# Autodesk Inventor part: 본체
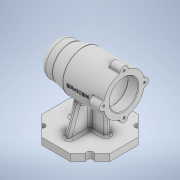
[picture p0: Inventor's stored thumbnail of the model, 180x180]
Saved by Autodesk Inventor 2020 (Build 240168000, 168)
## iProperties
Created: 2021-01
Part Number: 본체
Material: 일반
Document SubType Name: Modeling
Designer: PC2-15
Density: 1 g/cm^3
Appearance: 기본값
Author: PC2-15
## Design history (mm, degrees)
sketch "스케치1"
  geometry: L1 (-50, -20.711)-(-50, 20.711); L2 (-50, 20.711)-(-20.711, 50); L3 (-20.711, 50)-(20.711, 50); L4 (20.711, 50)-(50, 20.711); L5 (50, 20.711)-(50, -20.711); L6 (50, -20.711)-(20.711, -50); L7 (20.711, -50)-(-20.711, -50); L8 (-20.711, -50)-(-50, -20.711); 3 further points
  constraints: 16 end point, 1 coincident, 1 midpoint, 1 vertical alignment, 17 other
  dimensions: "d0" = 50 horizontal distance of L1.start point (0, -50)
extrude "돌출1" new body sketch "스케치1" distance "d1" = 10; taper "d2" = 0 deg
sketch "스케치2"
  geometry: L1 (50, 20.711)-(20.711, 50) reference; L2 (0, 0)-(35.355, 35.355); C1 r 4.5 at (35.355, 35.355); 1 further point
  constraints: 2 coincident, 2 end point, 1 centre point, 1 midpoint, 4 other
  dimensions: "d3" = 9 diameter of C1
extrude "돌출2" cut sketch "스케치2" distance "d4" = 10; taper "d5" = 0 deg
node "작업 평면1"
sketch "스케치3"
  geometry: C1 r 30 at (75, 0); 1 further point
  constraints: 1 centre point, 1 horizontal alignment
  dimensions: "d10" = 60 diameter of C1; "d11" = 75 distance of point (0, 0) C1.centre
extrude "돌출3" join sketch "스케치3" distance "d12" = 60; taper "d13" = 0 deg
sketch "스케치4"
  geometry: L1 (-10, 45)-(-10, 105) reference; L2 (-10, 105)-(-30, 100); L3 (-30, 100)-(-50, 100); L4 (-50, 100)-(-50, 75); L5 (-10, 75)-(-50, 75); 1 further point
  constraints: 8 end point, 2 horizontal, 1 midpoint, 1 perpendicular
  dimensions: "d14" = 40 distance from line of L1.end L4; "d15" = 20 distance from line of L2.end L4; "d16" = 50 diameter of L3 L5
revolve "회전1" sketch "스케치4" stored, may be unused: angle "d17" = 90 deg
sketch "스케치5"
  geometry: C1 r 6 at (30, 0); A1 r 6 centre (0, 30) between (5.97, 29.4) and (-5.97, 29.4); A2 r 6 centre (0, -30) between (-5.97, -29.4) and (5.97, -29.4); A3 r 6 centre (-30, 0) between (-29.4, 5.97) and (-29.4, -5.97); 4 further points
  constraints: 6 point on circle, 4 centre point, 2 horizontal alignment, 2 vertical alignment, 11 other
  dimensions: "d18" = 12 diameter of A1; "d19" = 12 diameter of C1; "d20" = 12 diameter of A2; "d22" = 12 diameter of A3
extrude "돌출4" join sketch "스케치5" distance "d23" = 16; taper "d24" = 0 deg
sketch "스케치6"
  geometry: L1 (-10, 45)-(-10, 105) reference; L2 (50, 69.03)-(34, 69.03) reference; L3 (34, 69.03)-(34, 80.97) reference; L4 (34, 80.97)-(50, 80.97) reference; L5 (50, 104.4)-(50, 80.97) reference; L6 (50, 104.4)-(34, 104.4) reference; L7 (34, 104.4)-(34, 104.4) reference; L8 (34, 104.4)-(50, 104.4) reference; L9 (50, 80.97)-(50, 104.4) reference; L10 (50, 80.97)-(34, 80.97) reference; L11 (34, 80.97)-(34, 69.03) reference; L12 (34, 69.03)-(50, 69.03) reference; L13 (50, 45.6)-(50, 69.03) reference; L14 (50, 45.6)-(34, 45.6) reference; L15 (34, 45.6)-(34, 45.6) reference; L16 (34, 45.6)-(50, 45.6) reference; L17 (50, 69.03)-(50, 45.6) reference; L18 (50, 69)-(50, 81) reference; L19 (50, 75)-(-36.955, 75); L20 (50, 80.97)-(50, 104.4) reference; L21 (50, 96)-(35, 96); L22 (35, 96)-(35, 99); L23 (35, 99)-(-7, 99); L24 (-7, 99)-(-7, 96); L25 (-7, 96)-(-19, 96); L26 (-19, 96)-(-19, 75); 2 further points
  constraints: 14 end point, 6 perpendicular, 2 point on line, 1 midpoint, 1 vertical
  dimensions: "d25" = 42 diameter of L21 L19; "d26" = 15 distance of L21.start L21.end; "d27" = 48 diameter of L23 L19; "d28" = 42 distance of L22.end L23.end; "d29" = 12 distance of L24.end L25.end; "d30" = 42 diameter of L25 L19
revolve "회전2" sketch "스케치6" stored, may be unused: angle "d31" = 90 deg
sketch "스케치7"
  geometry: L1 (-19, 54)-(-19, 96) reference; L2 (-19, 75)-(-50, 75); L3 (-50, 50)-(-50, 100) reference; L4 (-19, 92.5)-(-37, 92.5); L5 (-37, 92.5)-(-37, 91); L6 (-37, 91)-(-41, 91); L7 (-41, 91)-(-41, 85.5); L8 (-41, 85.5)-(-44, 85.5); L9 (-44, 85.5)-(-44, 75); 1 further point
  constraints: 14 end point, 4 perpendicular, 2 midpoint, 2 point on line, 1 horizontal, 1 vertical
  dimensions: "d32" = 18 distance of L4.start L4.end; "d33" = 35 diameter of L4 L2; "d34" = 4 distance of L5.end L6.end; "d35" = 32 diameter of L6 L2; "d36" = 3 distance of L7.end L8.end; "d37" = 21 diameter of L8 L2
revolve "회전3" sketch "스케치7" stored, may be unused: angle "d38" = 90 deg
sketch "스케치10"
  geometry: L1 (10, -20.711)-(10, 20.711) reference; L2 (10, 38.537)-(10, 30.855) reference; L3 (10, 20.711)-(10, 32.173) reference; L4 (10, -32.173)-(10, -20.711) reference; L5 (10, -30.855)-(10, -38.537) reference; L6 (52.293, 19.606)-(10, 35); L7 (52.293, -19.606)-(10, -35); L8 (0, 50)-(10, 50) reference; L9 (0, -50)-(10, -50) reference; L10 (10, 38.537)-(10, 50) reference; A1 r 30 centre (75, 0) between (52.293, 19.606) and (52.293, -19.606) reference; 1 further point
  constraints: 4 end point, 2 point on circle, 2 point on line
  dimensions: "d45" = 15 distance from line of L6.end L8; "d46" = 15 distance from line of L9 L7.end; "d47" = 110 deg angle of L6 L10; "d48" = 110 deg angle of L5 L7
extrude "돌출6" join sketch "스케치10" stored distance "d49" = 8; taper "d50" = 0 deg
fillet "모깎기11" dims "d104" = 3
sketch "스케치12"
  geometry: L1 (-30, 50)-(-10, 45) reference; L2 (-10, 45)-(34, 45) reference; L3 (-38.537, 10)-(-30.855, 10) reference; L4 (-20.711, 10)-(-32.173, 10) reference; L5 (20.711, 10)-(-20.711, 10) reference; L6 (-19.724, 47.431)-(-27, 10); L7 (-50, 0)-(-50, 10) reference; L8 (-38.537, 10)-(-50, 10) reference; L9 (-19.724, 47.431)-(-10, 45); L10 (-4, 52.293)-(-4, 10) reference; L11 (-4, 45)-(-4, 10); L12 (-4, 10)-(-27, 10); L13 (-10, 45)-(-4, 45); 1 further point
  constraints: 10 end point, 4 point on line, 1 collinear, 1 perpendicular
  dimensions: "d54" = 23 distance from line of L6.end L7; "d55" = 101 deg angle of L6 L8
feature "리브1" sketch "스케치12" dims "d56" = 1, "d57" = 8, "d58" = 0, "d59" = 0, "d60" = 1, "d61" = 1
node "작업 평면2"
fillet "모깎기1" dims "d63" = 10
fillet "모깎기2" dims "d70" = 0.3
fillet "모깎기3" dims "d71" = 3
chamfer "모따기3" distance "d72" = 1; stored, may be unused: second distance "d73" = 2, angle "d74" = 45 deg
fillet "모깎기4" dims "d75" = 3
sketch "스케치16"
  geometry: A1 r 6 centre (0, 105) between (5.97, 104.4) and (-5.97, 104.4) reference; 2 further points
  constraints: 1 coincident
hole "구멍1" sketch "스케치16" at (0, 105) diameter "d76" = 3.242; stored, may be unused: countersink angle "d80" = 90 deg, drill point angle "d82" = 118 deg; dims "d77" = 8, "d78" = 4, "d79" = 2, "d81" = 10
fillet "모깎기5" dims "d86" = 1
fillet "모깎기6" dims "d87" = 1
sketch "스케치17"
  geometry: L1 (27, 10)-(27, 37.964); L2 (50, 0)-(50, 10) reference; 1 further point
  constraints: 2 end point, 1 vertical
  dimensions: "d94" = 23 distance between parallel lines of L1 L2
feature "리브2" sketch "스케치17" dims "d95" = 1, "d96" = 8, "d97" = 0, "d98" = 0, "d99" = 1, "d100" = 1
fillet "모깎기8" dims "d101" = 3
fillet "모깎기9" dims "d102" = 3
fillet "모깎기10" dims "d103" = 3
sketch "스케치18"
  geometry: L1 (-8, 78)-(32, 78); L2 (32, 78)-(32, 72); L3 (32, 72)-(-8, 72); L4 (-8, 72)-(-8, 78); L5 (-8, 75)-(32, 75); L6 (12, 78)-(12, 72); L7 (50, 81.771)-(50, 104.226) reference; L8 (-20.711, 0)-(20.711, 0) reference; 1 further point
  constraints: 4 end point, 4 midpoint, 2 other
  dimensions: "d111" = 40 distance between parallel lines of L2 L4; "d112" = 6 distance between parallel lines of L3 L1; "d113" = 38 distance between parallel lines of L7 L6; "d114" = 75 distance between parallel lines of L8 L5
feature "엠보싱3" sketch "스케치18" dims "d6" = 40, "d115" = 0.5, "d116" = 0
node "솔리드1"
pattern_circular "원형 패턴1" dims angle "d7" = 360 deg
pattern_circular "원형 패턴2" dims angle "d84" = 360 deg
pattern_circular "원형 패턴3" dims angle "d89" = 360 deg
node "투영된 루프1"
other parameters: "d62" = 86.75
